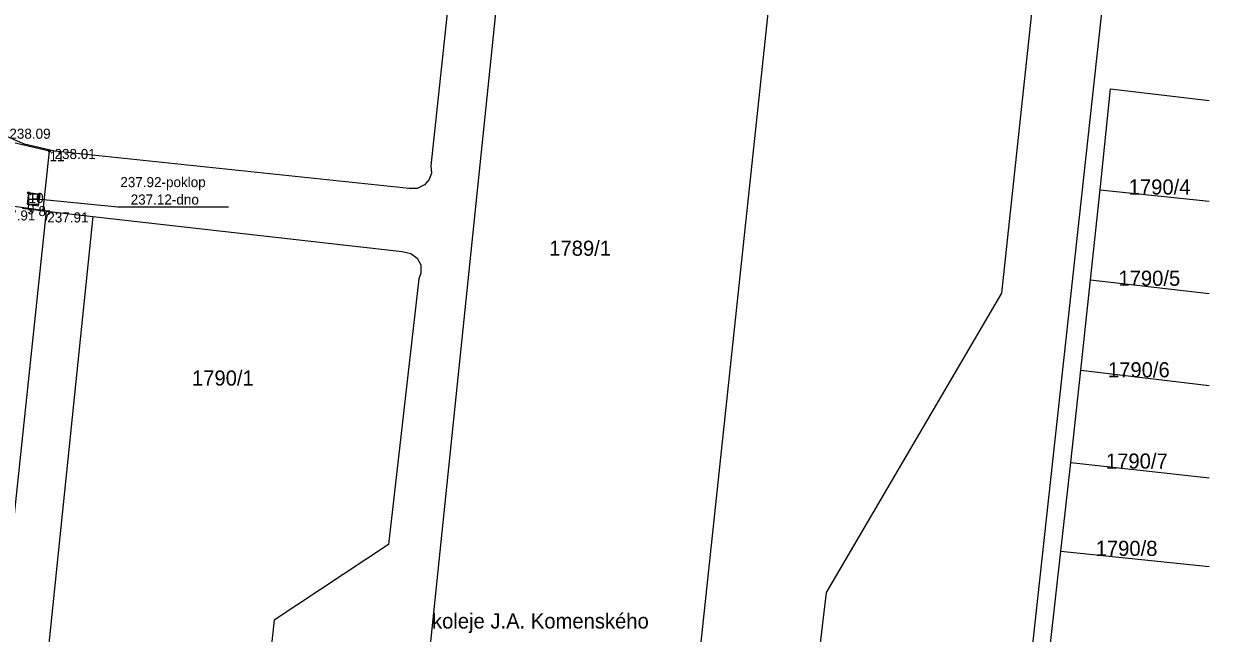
# Model space of a CAD drawing. Extents: x -596309 to -596099, y -1158697 to -1158513.
# Drawn here: x -596247.6 to -596188.8, y -1158640.1 to -1158609.8 of the extents above; entities that cross this region are included whole.
import ezdxf

# ---------------------------------------------------------------- set-up
doc = ezdxf.new("R2010")
doc.units = 0
for name, color, linetype in [('Vrstva 1', 7, 'Continuous'), ('Vrstva 10', 7, 'Continuous'), ('Vrstva 14', 7, 'Continuous'), ('Vrstva 2', 7, 'Continuous'), ('Vrstva 27', 7, 'Continuous'), ('Vrstva 3', 7, 'Continuous'), ('Vrstva 41', 7, 'Continuous'), ('Vrstva 58', 7, 'Continuous'), ('Vrstva 59', 7, 'Continuous')]:
    doc.layers.add(name, color=color, linetype=linetype)

msp = doc.modelspace()

# ---------------------------------------------------------------- linework, layer by layer
at = {"layer": 'Vrstva 1'}
for p, q in [((-596223.68, -1158581.67), (-596227.39, -1158616.86)), ((-596195.41, -1158589), (-596199.08, -1158623.18)), ((-596192.08, -1158590.8), (-596202.08, -1158682.08)), ((-596247.57, -1158615.8), (-596249.08, -1158615.14)), ((-596246.07, -1158616.14), (-596247.57, -1158615.8)), ((-596228.47, -1158617.99), (-596246.07, -1158616.14)), ((-596227.39, -1158616.86), (-596227.37, -1158617.23)), ((-596227.48, -1158617.55), (-596227.71, -1158617.81)), ((-596227.37, -1158617.23), (-596227.48, -1158617.55)), ((-596228.08, -1158617.99), (-596228.47, -1158617.99)), ((-596227.71, -1158617.81), (-596228.08, -1158617.99)), ((-596194.66, -1158622.52), (-596194.18, -1158618.06)), ((-596194.18, -1158618.06), (-596188.76, -1158618.618)), ((-596253.81, -1158688.53), (-596246.48, -1158619.11)), ((-596244.17, -1158619.38), (-596252.171, -1158697)), ((-596247.67, -1158618.96), (-596246.48, -1158619.11)), ((-596246.48, -1158619.11), (-596244.17, -1158619.38)), ((-596244.17, -1158619.38), (-596228.82, -1158621.12)), ((-596228.82, -1158621.12), (-596228.39, -1158621.21)), ((-596228.39, -1158621.21), (-596228.08, -1158621.45)), ((-596228.08, -1158621.45), (-596227.9, -1158621.78)), ((-596227.9, -1158621.78), (-596227.89, -1158622.19)), ((-596227.89, -1158622.19), (-596227.99, -1158622.47)), ((-596227.99, -1158622.47), (-596229.49, -1158635.66)), ((-596195.14, -1158627.01), (-596194.66, -1158622.52)), ((-596194.66, -1158622.52), (-596188.76, -1158623.208)), ((-596199.08, -1158623.18), (-596207.77, -1158638.04)), ((-596195.63, -1158631.59), (-596195.14, -1158627.01)), ((-596195.14, -1158627.01), (-596188.76, -1158627.766)), ((-596196.12, -1158635.98), (-596195.63, -1158631.59)), ((-596195.63, -1158631.59), (-596188.76, -1158632.341)), ((-596229.49, -1158635.66), (-596235.17, -1158639.41)), ((-596196.64, -1158640.56), (-596196.12, -1158635.98)), ((-596196.12, -1158635.98), (-596188.76, -1158636.742)), ((-596207.77, -1158638.04), (-596208.76, -1158646.12)), ((-596235.17, -1158639.41), (-596238.54, -1158669.8))]:
    msp.add_line(p, q, dxfattribs=at)
for points in [[(-596221.18, -1158580.18), (-596227.49, -1158641.27), (-596233.5, -1158640.71), (-596235.22, -1158657.39), (-596236.63, -1158670.04), (-596220.14, -1158671.86), (-596212.02, -1158672.68), (-596210.4, -1158659.8), (-596209.78, -1158653.62)], [(-596209.17, -1158649.66), (-596208.76, -1158646.12), (-596214.51, -1158645.47), (-596207.66, -1158581.2), (-596207, -1158581.28)], [(-596194.18, -1158618.06), (-596193.66, -1158613.05), (-596188.76, -1158613.633)]]:
    msp.add_lwpolyline(points, dxfattribs=at)
at = {"layer": 'Vrstva 10'}
msp.add_lwpolyline([(-596255.94, -1158625.49), (-596255.14, -1158623.17), (-596253.63, -1158621.09), (-596251.82, -1158619.81), (-596249.8, -1158619.04), (-596248.08, -1158618.86), (-596246.63, -1158619.07), (-596246.32, -1158616.14), (-596248.59, -1158615.61), (-596250.53, -1158614.58), (-596252.22, -1158612.92), (-596253.51, -1158610.57), (-596253.93, -1158608.27)], dxfattribs=at)
at = {"layer": 'Vrstva 2'}
msp.add_lwpolyline([(-596237.445, -1158618.925), (-596242.924, -1158618.925), (-596247.119, -1158618.508)], dxfattribs=at)
for centre in [(-596246.32, -1158616.14), (-596247.36, -1158618.21), (-596246.63, -1158619.07)]:
    msp.add_circle(centre, 0.05, dxfattribs=at)
at = {"layer": 'Vrstva 27'}
msp.add_line((-596247.36, -1158618.515), (-596246.86, -1158618.515), dxfattribs=at)
msp.add_lwpolyline([(-596247.36, -1158618.765), (-596246.86, -1158618.765), (-596246.86, -1158618.265), (-596247.36, -1158618.265)], close=True, dxfattribs=at)
at = {"layer": 'Vrstva 3'}
for p, q in [((-596246.32, -1158616.14), (-596246.319, -1158616.14)), ((-596247.36, -1158618.21), (-596247.359, -1158618.21)), ((-596247.44, -1158618.77), (-596247.439, -1158618.77)), ((-596246.87, -1158618.86), (-596246.869, -1158618.86)), ((-596246.63, -1158619.07), (-596246.629, -1158619.07))]:
    msp.add_line(p, q, dxfattribs=at)
at = {"layer": 'Vrstva 58'}
msp.add_lwpolyline([(-596247.36, -1158618.21), (-596247.44, -1158618.77), (-596246.869, -1158618.852), (-596246.789, -1158618.292)], close=True, dxfattribs=at)

# ---------------------------------------------------------------- texts
at = {"layer": 'Vrstva 14'}
for s, p in [('1790/4', (-596192.76, -1158618.29)), ('1789/1', (-596221.52, -1158621.33)), ('1790/5', (-596193.27, -1158622.82)), ('1790/1', (-596239.253, -1158627.77)), ('1790/6', (-596193.79, -1158627.36)), ('1790/7', (-596193.89, -1158631.89)), ('1790/8', (-596194.4, -1158636.22))]:
    msp.add_text(s, height=0.75, dxfattribs=at).set_placement(p)
at = {"layer": 'Vrstva 2'}
for s, p in [('238.09', (-596248.315, -1158615.523)), ('238.01', (-596246.074, -1158616.53)), ('237.92-poklop', (-596242.808, -1158617.925)), ('237.12-dno', (-596242.294, -1158618.789)), ('237.91', (-596249.069, -1158619.577)), ('237.91', (-596246.432, -1158619.675))]:
    msp.add_text(s, height=0.5, dxfattribs=at).set_placement(p)
at = {"layer": 'Vrstva 41'}
msp.add_text('koleje J.A. Komenského', height=0.75, dxfattribs=at).set_placement((-596227.339, -1158639.823))
at = {"layer": 'Vrstva 59'}
for s, p in [('11', (-596246.32, -1158616.64)), ('10', (-596247.36, -1158618.71)), ('9', (-596247.44, -1158619.27)), ('8', (-596246.87, -1158619.36)), ('7', (-596246.63, -1158619.57))]:
    msp.add_text(s, height=0.5, dxfattribs=at).set_placement(p)

doc.saveas('drawing.dxf')
